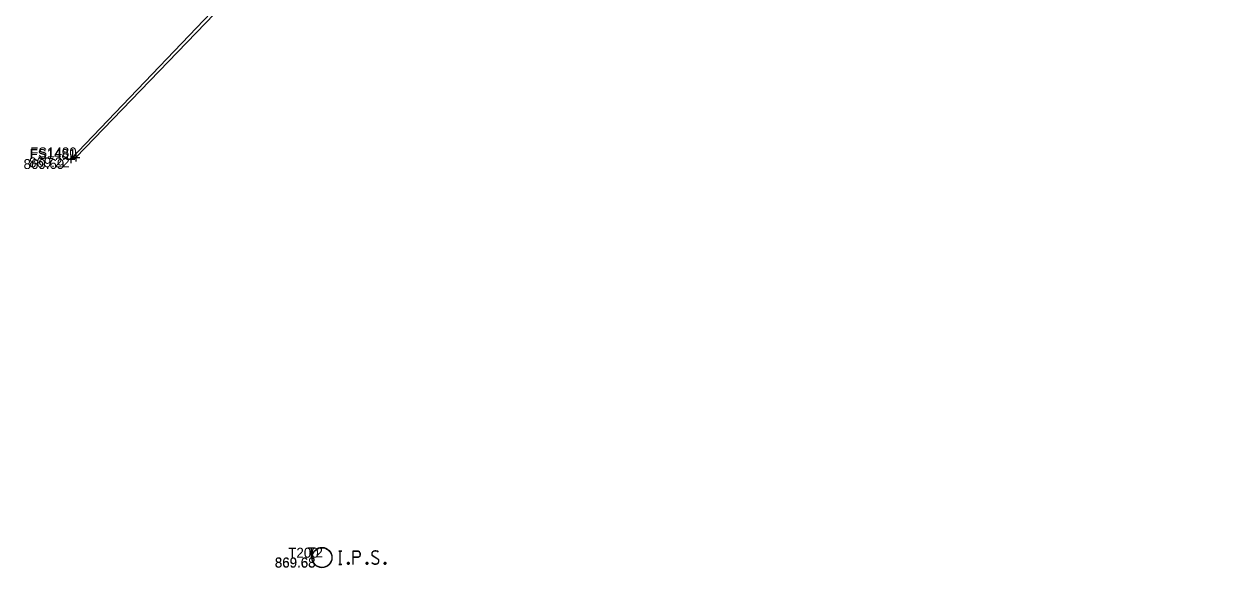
# Model space of a CAD drawing. Extents: x 1479420 to 1479833, y 379731 to 380103.
# Drawn here: x 1479447.3 to 1479593, y 379731.3 to 379796.9 of the extents above; entities that cross this region are included whole.
import ezdxf

# ---------------------------------------------------------------- set-up
doc = ezdxf.new("R2010")
doc.units = 0
for name, color, linetype in [('PV_X_Curb', 7, 'Continuous'), ('SV_P_Mon_Cells_Set', 7, 'Continuous'), ('SV_X_Shot_Marker', 7, 'Continuous'), ('SV_X_Text_Elevation', 7, 'Continuous'), ('SV_X_Text_Name', 7, 'Continuous')]:
    doc.layers.add(name, color=color, linetype=linetype)

msp = doc.modelspace()

# ---------------------------------------------------------------- linework, layer by layer
at = {"layer": 'PV_X_Curb'}
for points in [[(1479601.32, 379856.89), (1479590.52, 379858.04), (1479580.72, 379858.06), (1479571.15, 379856.79), (1479561.29, 379853.75), (1479553.09, 379850.7), (1479544.73, 379845.63), (1479537.42, 379839.85), (1479530.35, 379833.14), (1479518.15, 379820.18), (1479506.75, 379808.8), (1479505.04, 379808.13), (1479502.74, 379808.99), (1479490.36, 379819.72), (1479452.91, 379780.6)], [(1479601.35, 379856.37), (1479590.36, 379857.44), (1479580.92, 379857.48), (1479571.06, 379856.27), (1479561.56, 379853.27), (1479553.28, 379850.19), (1479545.2, 379845.23), (1479537.87, 379839.39), (1479530.79, 379832.84), (1479518.52, 379819.83), (1479508.59, 379809.05), (1479504.77, 379807.6), (1479502.38, 379808.45), (1479490.37, 379818.94), (1479453.51, 379780.8)]]:
    msp.add_lwpolyline(points, dxfattribs=at)
at = {"layer": 'SV_P_Mon_Cells_Set'}
for points in [[(1479485.23, 379733.35), (1479485.58, 379733.35)], [(1479485.24, 379733.39), (1479485.59, 379733.39)], [(1479485.4, 379731.75), (1479485.4, 379733.35)], [(1479485.42, 379731.79), (1479485.42, 379733.39)], [(1479486.97, 379731.75), (1479486.97, 379733.35), (1479487.5, 379733.35), (1479487.55, 379733.34), (1479487.63, 379733.32), (1479487.66, 379733.29), (1479487.7, 379733.27), (1479487.74, 379733.2), (1479487.77, 379733.14), (1479487.79, 379733.04), (1479487.79, 379732.89), (1479487.78, 379732.84), (1479487.76, 379732.76), (1479487.72, 379732.67), (1479487.67, 379732.64), (1479487.64, 379732.61), (1479487.58, 379732.58), (1479487.5, 379732.57), (1479486.97, 379732.57)], [(1479486.98, 379731.79), (1479486.98, 379733.39), (1479487.51, 379733.39), (1479487.56, 379733.38), (1479487.64, 379733.35), (1479487.68, 379733.33), (1479487.71, 379733.3), (1479487.75, 379733.24), (1479487.79, 379733.17), (1479487.81, 379733.07), (1479487.81, 379732.92), (1479487.8, 379732.87), (1479487.77, 379732.8), (1479487.73, 379732.71), (1479487.69, 379732.67), (1479487.65, 379732.65), (1479487.6, 379732.62), (1479487.51, 379732.61), (1479486.98, 379732.61)], [(1479489.98, 379733.24), (1479489.95, 379733.27), (1479489.92, 379733.29), (1479489.82, 379733.33), (1479489.7, 379733.35), (1479489.61, 379733.35), (1479489.58, 379733.35), (1479489.44, 379733.32), (1479489.32, 379733.24), (1479489.24, 379733.14), (1479489.22, 379733.04), (1479489.22, 379732.96), (1479489.24, 379732.86), (1479489.33, 379732.77), (1479489.93, 379732.4), (1479489.99, 379732.35), (1479490.01, 379732.3), (1479490.03, 379732.22), (1479490.03, 379732.14), (1479490.02, 379732.07), (1479490.01, 379732.02), (1479489.99, 379731.96), (1479489.97, 379731.9), (1479489.94, 379731.87), (1479489.91, 379731.83), (1479489.88, 379731.8), (1479489.83, 379731.78), (1479489.8, 379731.77), (1479489.7, 379731.75), (1479489.55, 379731.75), (1479489.45, 379731.78), (1479489.3, 379731.87), (1479489.22, 379731.94)], [(1479489.99, 379733.28), (1479489.97, 379733.3), (1479489.93, 379733.33), (1479489.84, 379733.36), (1479489.71, 379733.39), (1479489.63, 379733.39), (1479489.59, 379733.39), (1479489.45, 379733.35), (1479489.33, 379733.28), (1479489.25, 379733.17), (1479489.23, 379733.07), (1479489.23, 379733), (1479489.25, 379732.9), (1479489.34, 379732.81), (1479489.95, 379732.43), (1479490, 379732.38), (1479490.02, 379732.33), (1479490.04, 379732.26), (1479490.04, 379732.18), (1479490.03, 379732.1), (1479490.02, 379732.05), (1479490, 379731.99), (1479489.98, 379731.94), (1479489.96, 379731.9), (1479489.92, 379731.86), (1479489.89, 379731.84), (1479489.85, 379731.81), (1479489.81, 379731.8), (1479489.71, 379731.79), (1479489.56, 379731.79), (1479489.46, 379731.81), (1479489.32, 379731.9), (1479489.23, 379731.98)], [(1479485.23, 379731.75), (1479485.58, 379731.75)], [(1479485.24, 379731.79), (1479485.59, 379731.79)], [(1479486.36, 379731.97), (1479486.42, 379731.97), (1479486.45, 379731.94), (1479486.48, 379731.89), (1479486.48, 379731.83), (1479486.45, 379731.78), (1479486.42, 379731.75), (1479486.36, 379731.75), (1479486.33, 379731.78), (1479486.3, 379731.83), (1479486.3, 379731.89), (1479486.33, 379731.94), (1479486.36, 379731.97)], [(1479486.37, 379732), (1479486.43, 379732), (1479486.46, 379731.98), (1479486.5, 379731.93), (1479486.5, 379731.86), (1479486.46, 379731.81), (1479486.43, 379731.79), (1479486.37, 379731.79), (1479486.34, 379731.81), (1479486.31, 379731.86), (1479486.31, 379731.93), (1479486.34, 379731.98), (1479486.37, 379732)], [(1479488.61, 379731.97), (1479488.67, 379731.97), (1479488.7, 379731.94), (1479488.73, 379731.89), (1479488.73, 379731.83), (1479488.7, 379731.78), (1479488.67, 379731.75), (1479488.61, 379731.75), (1479488.58, 379731.78), (1479488.54, 379731.83), (1479488.54, 379731.89), (1479488.58, 379731.94), (1479488.61, 379731.97)], [(1479488.62, 379732), (1479488.68, 379732), (1479488.71, 379731.98), (1479488.74, 379731.93), (1479488.74, 379731.86), (1479488.71, 379731.81), (1479488.68, 379731.79), (1479488.62, 379731.79), (1479488.59, 379731.81), (1479488.56, 379731.86), (1479488.56, 379731.93), (1479488.59, 379731.98), (1479488.62, 379732)], [(1479490.79, 379731.97), (1479490.85, 379731.97), (1479490.88, 379731.94), (1479490.91, 379731.89), (1479490.91, 379731.83), (1479490.88, 379731.78), (1479490.85, 379731.75), (1479490.79, 379731.75), (1479490.76, 379731.78), (1479490.73, 379731.83), (1479490.73, 379731.89), (1479490.76, 379731.94), (1479490.79, 379731.97)], [(1479490.81, 379732), (1479490.86, 379732), (1479490.89, 379731.98), (1479490.93, 379731.93), (1479490.93, 379731.86), (1479490.89, 379731.81), (1479490.86, 379731.79), (1479490.81, 379731.79), (1479490.77, 379731.81), (1479490.74, 379731.86), (1479490.74, 379731.93), (1479490.77, 379731.98), (1479490.81, 379732)]]:
    msp.add_lwpolyline(points, dxfattribs=at)
for centre in [(1479483.21, 379732.55), (1479483.22, 379732.59)]:
    msp.add_circle(centre, 1.2, dxfattribs=at)
at = {"layer": 'SV_X_Shot_Marker'}
for p, q in [((1479452.91, 379781.1), (1479452.91, 379780.1)), ((1479453.51, 379781.3), (1479453.51, 379780.3)), ((1479452.41, 379780.6), (1479453.41, 379780.6)), ((1479452.91, 379780.6), (1479452.91, 379780.6)), ((1479453.01, 379780.8), (1479454.01, 379780.8)), ((1479453.51, 379780.8), (1479453.51, 379780.8))]:
    msp.add_line(p, q, dxfattribs=at)

# ---------------------------------------------------------------- texts
at = {"layer": 'SV_X_Text_Elevation'}
for s, p in [('869.69', (1479447.22, 379779.4)), ('869.22', (1479447.88, 379779.6)), ('869.68', (1479477.52, 379731.35)), ('869.63', (1479477.54, 379731.39))]:
    msp.add_text(s, height=1.2, dxfattribs=at).set_placement(p)
at = {"layer": 'SV_X_Text_Name'}
for s, p in [('FS1481', (1479447.95, 379780.6)), ('FS1480', (1479448.01, 379780.8)), ('T200', (1479479.15, 379732.55)), ('T2', (1479481.45, 379732.59))]:
    msp.add_text(s, height=1.2, dxfattribs=at).set_placement(p)

doc.saveas('drawing.dxf')
